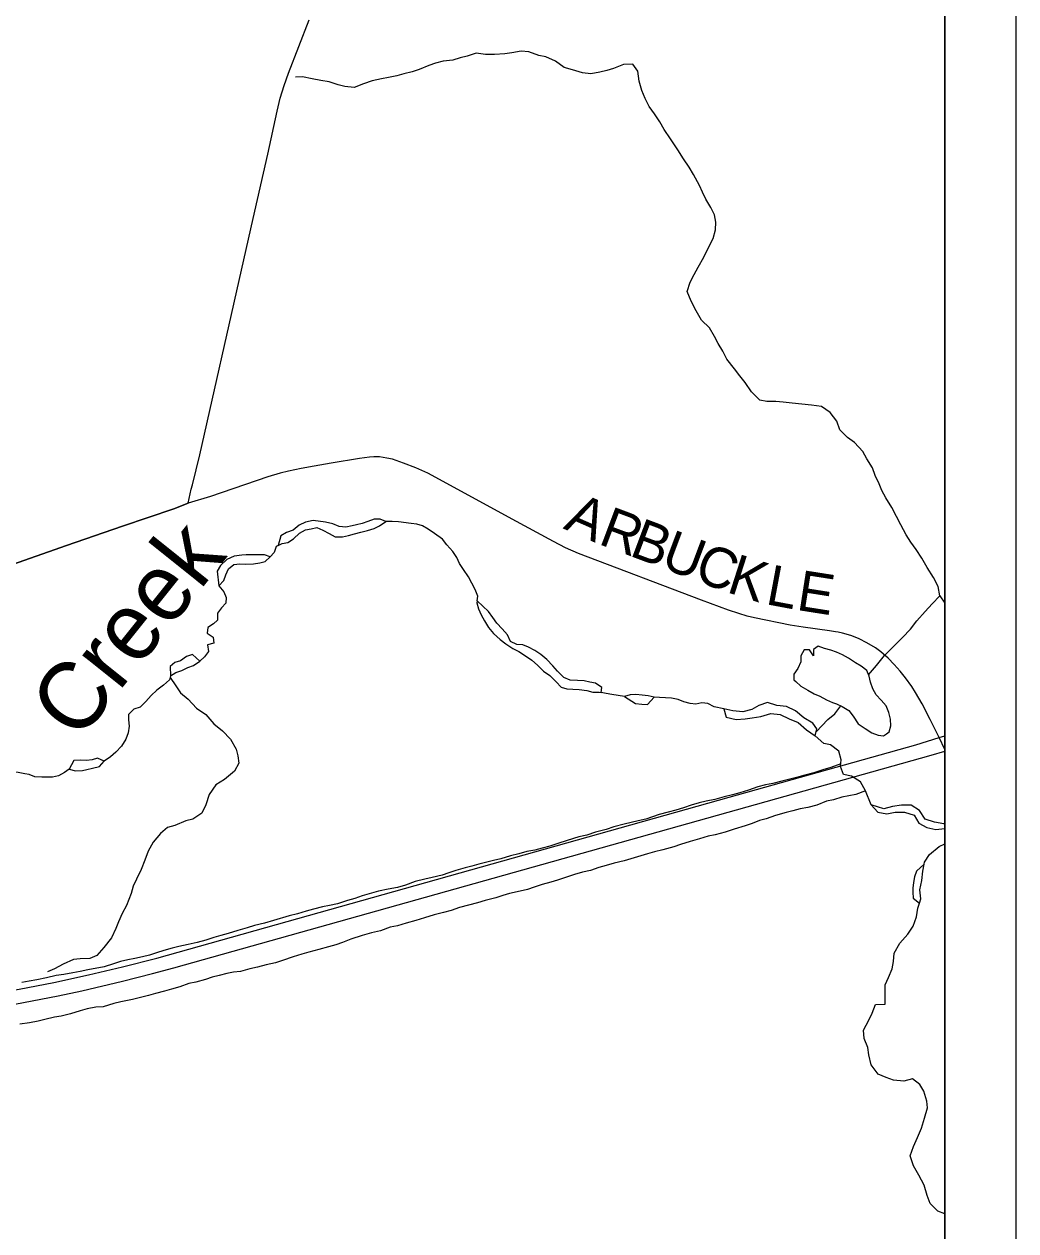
# Model space of a CAD drawing. Extents: x 0 to 36.5, y 0 to 25.3.
# Drawn here: x 7.602 to 9, y 17.597 to 19.299 of the extents above; entities that cross this region are included whole.
import ezdxf

# ---------------------------------------------------------------- set-up
doc = ezdxf.new("R2010")
doc.units = 0
for name, color, linetype in [('DV_X_Township_Line', 7, 'Continuous'), ('GM_X_County_Road', 7, 'Continuous'), ('GM_X_County_Road_Text', 7, 'Continuous'), ('GM_X_Interstate_Route', 7, 'Continuous'), ('GM_X_Major_River', 7, 'Continuous'), ('GM_X_Major_River_Text', 7, 'Continuous'), ('GM_X_Minor_Lake', 7, 'Continuous'), ('GM_X_Minor_River', 7, 'Continuous'), ('GM_X_State_Route', 7, 'Continuous'), ('SH_Cut_Line', 7, 'Continuous'), ('SH_Data', 7, 'Continuous')]:
    doc.layers.add(name, color=color, linetype=linetype)

msp = doc.modelspace()

# ---------------------------------------------------------------- linework, layer by layer
at = {"layer": 'DV_X_Township_Line'}
msp.add_lwpolyline([(8.9, 14.8674), (8.9, 20.9), (6.9868, 20.9), (6.9145, 19.9406), (6.7968, 18.6079), (6.7478, 17.9113), (6.7464, 17.8914), (6.7165, 17.4645), (6.7158, 17.4536), (6.6079, 15.9978), (6.8419, 15.8878), (7.703, 15.458), (7.7552, 15.432), (7.7814, 15.4189), (7.8139, 15.4027), (8.0723, 15.2737), (8.5228, 15.0526)], close=True, dxfattribs=at)
at = {"layer": 'GM_X_County_Road'}
for points in [[(8.7456, 18.4416), (8.7371, 18.4431), (8.7003, 18.448), (8.6819, 18.451), (8.6313, 18.4615), (8.6212, 18.4639), (8.6093, 18.4673), (8.5947, 18.4723), (8.5568, 18.4864), (8.3835, 18.5523), (8.3649, 18.5603), (8.348, 18.5689), (8.2899, 18.6003), (8.1927, 18.6538), (8.1709, 18.6653), (8.154, 18.6729), (8.1368, 18.6796), (8.1209, 18.6849), (8.1132, 18.6867), (8.1026, 18.6882), (8.0947, 18.6883), (8.0886, 18.6879), (8.0747, 18.6862), (8.0344, 18.6797), (8.0104, 18.6754), (7.9925, 18.672), (7.9746, 18.6682), (7.9628, 18.6653), (7.9453, 18.6601), (7.8645, 18.6327), (7.8329, 18.6231)], [(7.8329, 18.6231), (7.8129, 18.6149), (7.7406, 18.5907), (7.6614, 18.5636), (7.55, 18.5246), (7.4901, 18.5041)], [(8.9, 18.2759), (8.8917, 18.2927), (8.8791, 18.318), (8.8677, 18.34), (8.8584, 18.3561), (8.8531, 18.3644), (8.8444, 18.3766), (8.8368, 18.3863), (8.8286, 18.3956), (8.8199, 18.4044), (8.8095, 18.4134), (8.802, 18.419), (8.7901, 18.4263), (8.7789, 18.4319), (8.7732, 18.4342), (8.7674, 18.4363), (8.7554, 18.4396), (8.7494, 18.441), (8.7456, 18.4416)]]:
    msp.add_lwpolyline(points, dxfattribs=at)
at = {"layer": 'GM_X_Interstate_Route'}
for points in [[(6.2743, 17.9219), (6.7481, 17.9108), (7.1122, 17.9021), (7.1623, 17.9009), (7.1809, 17.9008), (7.2306, 17.9013), (7.2616, 17.9022), (7.2989, 17.9039), (7.3609, 17.9079), (7.398, 17.9109), (7.4475, 17.9161), (7.5029, 17.923), (7.5582, 17.9316), (7.5949, 17.938), (7.6437, 17.9474), (7.6923, 17.9578), (7.7406, 17.9692), (7.7887, 17.9816), (8.5958, 18.2085), (8.859, 18.2822), (8.8917, 18.2927), (8.9, 18.2951)], [(7.1025, 17.8824), (7.1065, 17.8823), (7.162, 17.881), (7.1931, 17.881), (7.2179, 17.8813), (7.2552, 17.8823), (7.2924, 17.8836), (7.3479, 17.887), (7.3916, 17.8905), (7.4533, 17.8971), (7.5027, 17.9033), (7.5457, 17.9096), (7.5886, 17.9168), (7.6497, 17.9284), (7.6832, 17.9355), (7.7405, 17.9489), (7.7826, 17.9598), (7.8126, 17.968), (8.8804, 18.2679), (8.9, 18.2733)]]:
    msp.add_lwpolyline(points, dxfattribs=at)
at = {"layer": 'GM_X_Major_River'}
for points in [[(8.1115, 18.597), (8.1039, 18.6004), (8.0951, 18.6005), (8.0864, 18.5974), (8.0784, 18.5944), (8.0704, 18.5926), (8.064, 18.591), (8.0552, 18.5892), (8.0461, 18.5903), (8.037, 18.5938), (8.0268, 18.5961), (8.0093, 18.5984), (7.9986, 18.5962), (7.9895, 18.592), (7.9811, 18.5852), (7.9716, 18.5818), (7.9636, 18.5769), (7.96, 18.5635)], [(8.2403, 18.4854), (8.2414, 18.4921), (8.2377, 18.5013), (8.2327, 18.5104), (8.2282, 18.5191), (8.221, 18.5294), (8.2157, 18.5378), (8.2116, 18.5466), (8.2063, 18.5549), (8.1976, 18.5641), (8.1915, 18.5721), (8.1805, 18.5801), (8.1714, 18.5866), (8.1635, 18.5911), (8.1555, 18.5934), (8.1472, 18.5942), (8.1297, 18.5966), (8.1206, 18.5973), (8.1115, 18.597)], [(7.96, 18.5635), (7.9655, 18.5662), (7.9735, 18.5674), (7.9815, 18.573), (7.9899, 18.5806), (7.9982, 18.5855), (8.0062, 18.587), (8.0146, 18.5889), (8.0229, 18.5851), (8.032, 18.5801), (8.0404, 18.5755), (8.0506, 18.5755), (8.059, 18.5774), (8.0677, 18.58), (8.0765, 18.5823), (8.086, 18.5845), (8.0951, 18.5872), (8.1027, 18.5913), (8.1115, 18.597)], [(7.96, 18.5635), (7.9571, 18.5621), (7.9541, 18.5537), (7.9487, 18.5473)], [(7.9487, 18.5473), (7.9408, 18.55), (7.9309, 18.5504), (7.9233, 18.55), (7.9146, 18.5501), (7.9085, 18.5497), (7.8978, 18.5482), (7.8876, 18.5437), (7.8784, 18.535), (7.8739, 18.527), (7.8761, 18.5065)], [(7.8761, 18.5065), (7.8833, 18.514), (7.886, 18.522), (7.8898, 18.5304), (7.8974, 18.5364), (7.9058, 18.5375), (7.9141, 18.5371), (7.9252, 18.5375), (7.9339, 18.539), (7.9415, 18.5409), (7.9487, 18.5473)], [(7.8761, 18.5065), (7.8833, 18.4981), (7.8867, 18.4901), (7.8859, 18.4821), (7.8798, 18.4753), (7.8741, 18.4681), (7.8744, 18.4582), (7.8687, 18.4529), (7.8607, 18.4476), (7.8599, 18.44), (7.8683, 18.4343)], [(8.2403, 18.4854), (8.2399, 18.4826), (8.2421, 18.4743), (8.2463, 18.4655), (8.2508, 18.4571), (8.2565, 18.4476), (8.2637, 18.4392), (8.2728, 18.4309), (8.2811, 18.4247), (8.2906, 18.4183), (8.2993, 18.4137), (8.3084, 18.408), (8.3175, 18.4015), (8.3255, 18.3946), (8.3342, 18.3862), (8.3429, 18.3801), (8.352, 18.3713), (8.3588, 18.3637), (8.3671, 18.3614), (8.3755, 18.361), (8.3842, 18.3602), (8.3952, 18.3587), (8.4036, 18.3568), (8.4127, 18.3564), (8.4153, 18.3559)], [(8.4153, 18.3559), (8.4161, 18.3632), (8.4074, 18.3693), (8.3995, 18.3708), (8.3911, 18.3724), (8.382, 18.3732), (8.3717, 18.3736), (8.3626, 18.3774), (8.3535, 18.3862), (8.3471, 18.3938), (8.3388, 18.4025), (8.3301, 18.4098), (8.3217, 18.4151), (8.313, 18.4201), (8.3047, 18.4232), (8.2963, 18.4236), (8.2876, 18.4282), (8.283, 18.4373), (8.2755, 18.446), (8.2683, 18.454), (8.2626, 18.462), (8.2562, 18.4704), (8.2403, 18.4854)], [(7.8683, 18.4343), (7.869, 18.4255), (7.8602, 18.4233), (7.8617, 18.4138), (7.856, 18.4062), (7.8495, 18.4005)], [(7.8495, 18.4005), (7.8389, 18.4097), (7.8306, 18.407), (7.8222, 18.4006), (7.8142, 18.3983), (7.8077, 18.393), (7.8081, 18.3797)], [(7.8081, 18.3797), (7.8157, 18.3843), (7.8241, 18.3873), (7.8324, 18.3914), (7.8404, 18.3941), (7.8495, 18.4005)], [(7.8081, 18.3797), (7.8065, 18.374), (7.7982, 18.3664), (7.789, 18.3596), (7.781, 18.3517), (7.7734, 18.3433), (7.7654, 18.3354), (7.7563, 18.3327), (7.749, 18.3252), (7.749, 18.3176), (7.7498, 18.3088), (7.7486, 18.2993), (7.7451, 18.2902), (7.739, 18.2803), (7.731, 18.272), (7.7234, 18.2656), (7.7147, 18.2591)], [(8.4484, 18.3506), (8.4393, 18.3517), (8.4305, 18.3533), (8.4222, 18.3548), (8.4153, 18.3559)], [(8.4898, 18.3497), (8.4814, 18.3516), (8.4731, 18.3524), (8.4644, 18.3532), (8.4564, 18.3528), (8.4484, 18.3506)], [(8.4484, 18.3506), (8.4639, 18.3406), (8.4727, 18.3398), (8.4806, 18.3394), (8.4898, 18.3497)], [(8.5883, 18.3332), (8.5748, 18.3361), (8.5657, 18.3407), (8.5574, 18.3415), (8.549, 18.3396), (8.541, 18.3404), (8.5319, 18.3431), (8.524, 18.3462), (8.5145, 18.3481), (8.5061, 18.3485), (8.4974, 18.3489), (8.4898, 18.3497)], [(8.7171, 18.2948), (8.7193, 18.3047), (8.7135, 18.3131), (8.701, 18.3204), (8.6893, 18.3304), (8.6764, 18.3366), (8.6631, 18.3378), (8.6499, 18.3418), (8.6377, 18.3377), (8.6278, 18.3321), (8.6148, 18.3288), (8.6011, 18.3304), (8.5883, 18.3332)], [(8.5883, 18.3332), (8.5916, 18.3214), (8.6056, 18.3182), (8.6185, 18.3188), (8.628, 18.3203), (8.6406, 18.3221), (8.6543, 18.3265), (8.6676, 18.3249), (8.6805, 18.3191), (8.6929, 18.3136), (8.705, 18.3036), (8.7171, 18.2948)], [(8.7961, 18.1979), (8.7878, 18.2174), (8.7811, 18.23), (8.7683, 18.2381), (8.7569, 18.2405), (8.7528, 18.2519), (8.7536, 18.2614), (8.7503, 18.2736), (8.7386, 18.2821), (8.7292, 18.2841), (8.7171, 18.2948)], [(7.7147, 18.2591), (7.7052, 18.2633), (7.6976, 18.2611), (7.6896, 18.26), (7.6809, 18.2607), (7.6717, 18.26), (7.6653, 18.2479)], [(7.6653, 18.2479), (7.674, 18.2456), (7.6839, 18.2459), (7.6899, 18.2474), (7.6983, 18.2493), (7.7078, 18.2516), (7.7147, 18.2591)], [(7.6653, 18.2479), (7.6584, 18.2433), (7.65, 18.2384), (7.6417, 18.2365), (7.6265, 18.2366), (7.617, 18.2374), (7.6086, 18.2404), (7.6026, 18.2416), (7.5931, 18.2435), (7.5847, 18.2439), (7.5764, 18.2432), (7.5676, 18.2451), (7.5593, 18.2467), (7.5467, 18.244)], [(8.7961, 18.1979), (8.8054, 18.1872), (8.8179, 18.1852), (8.8297, 18.1874), (8.843, 18.1873), (8.8567, 18.1833), (8.863, 18.1719), (8.8744, 18.1657), (8.8873, 18.1629), (8.8998, 18.1643), (8.9, 18.1638)], [(8.9, 18.1701), (8.8983, 18.1708), (8.8855, 18.1732), (8.8722, 18.1775), (8.8639, 18.1897), (8.8522, 18.1971), (8.8389, 18.1972), (8.826, 18.1954), (8.8138, 18.1921), (8.7961, 18.1979)], [(8.8707, 18.114), (8.8713, 18.1171), (8.8782, 18.1277), (8.8919, 18.1392), (8.9, 18.1427)], [(8.8707, 18.114), (8.8601, 18.1043), (8.8571, 18.0963), (8.8555, 18.0883), (8.8548, 18.0804), (8.8547, 18.0747), (8.8551, 18.0659), (8.8642, 18.0592)], [(8.8642, 18.0592), (8.8662, 18.0651), (8.8648, 18.078), (8.8676, 18.0909), (8.8689, 18.1042), (8.8707, 18.114)], [(8.9, 17.6209), (8.89, 17.6246), (8.8794, 17.6354), (8.875, 17.6468), (8.8706, 17.6613), (8.8631, 17.6754), (8.8556, 17.6888), (8.8508, 17.7029), (8.8555, 17.7158), (8.8613, 17.7287), (8.8671, 17.7419), (8.8714, 17.7559), (8.8753, 17.7704), (8.8747, 17.7799), (8.8702, 17.794), (8.8646, 17.8035), (8.8541, 17.8112), (8.8419, 17.8079), (8.8274, 17.8096), (8.8172, 17.8131), (8.8059, 17.8181), (8.7961, 17.8311), (8.7928, 17.8452), (8.7914, 17.8555), (8.7862, 17.8681), (8.7852, 17.8799), (8.7925, 17.8939), (8.7972, 17.9041), (8.8022, 17.9162), (8.8155, 17.9165), (8.8157, 17.9438), (8.8204, 17.9541), (8.8255, 17.9666), (8.8274, 17.9768), (8.8283, 17.9886), (8.8364, 18.0026), (8.8479, 18.0154), (8.8553, 18.0268), (8.8599, 18.0396), (8.8616, 18.0518), (8.8642, 18.0592)]]:
    msp.add_lwpolyline(points, dxfattribs=at)
at = {"layer": 'GM_X_Minor_Lake'}
for points in [[(8.8174, 18.2979), (8.8212, 18.3005), (8.8235, 18.3092), (8.8232, 18.3187), (8.8209, 18.3279), (8.8172, 18.3374), (8.81, 18.3454), (8.8028, 18.353), (8.7983, 18.3614), (8.7949, 18.3709), (8.793, 18.3793), (8.79, 18.3872), (8.782, 18.3933), (8.7737, 18.3979), (8.7642, 18.4044), (8.7555, 18.4094), (8.7471, 18.4128), (8.7392, 18.4159), (8.7301, 18.4182), (8.7213, 18.4216), (8.7149, 18.4167), (8.7148, 18.4076), (8.7092, 18.4163), (8.7016, 18.4164), (8.6966, 18.408), (8.6966, 18.3993), (8.6927, 18.3898), (8.687, 18.3818), (8.687, 18.3742)], [(8.687, 18.3742), (8.6897, 18.3716), (8.6968, 18.3651), (8.7067, 18.3594), (8.7154, 18.3544), (8.7238, 18.3509), (8.7329, 18.346), (8.7416, 18.3422), (8.7473, 18.3399), (8.7549, 18.3364), (8.7647, 18.3307), (8.7708, 18.3227), (8.7776, 18.312), (8.7874, 18.3052), (8.7969, 18.2991), (8.8057, 18.296), (8.8136, 18.2952), (8.8174, 18.2979)]]:
    msp.add_lwpolyline(points, dxfattribs=at)
at = {"layer": 'GM_X_Minor_River'}
msp.add_line((8.8928, 18.4922), (8.9, 18.4823), dxfattribs=at)
for points in [[(8.206, 19.2476), (8.1924, 19.2461), (8.1817, 19.2435), (8.1722, 19.2401), (8.1585, 19.2345), (8.1486, 19.2314), (8.1372, 19.2284), (8.127, 19.2258), (8.1156, 19.2232), (8.1057, 19.2213), (8.0924, 19.2187), (8.0802, 19.2145), (8.0669, 19.2093), (8.054, 19.2104), (8.0445, 19.2131), (8.032, 19.217), (8.0202, 19.2189), (8.0077, 19.2212), (7.994, 19.2243), (7.9842, 19.2239)], [(8.7923, 18.3812), (8.8037, 18.394), (8.8147, 18.4085), (8.8265, 18.4202), (8.8403, 18.4335), (8.8513, 18.4452), (8.8605, 18.457), (8.8723, 18.4702), (8.8822, 18.4812), (8.8928, 18.4922), (8.8906, 18.5055), (8.8838, 18.5181), (8.8751, 18.5322), (8.8672, 18.5455), (8.8592, 18.5577), (8.8517, 18.5683), (8.8452, 18.5782), (8.8377, 18.5923), (8.8316, 18.6041), (8.8252, 18.6171), (8.8165, 18.6308), (8.8112, 18.6407), (8.8071, 18.6502), (8.8014, 18.6623), (8.7977, 18.673), (8.7897, 18.6856), (8.7841, 18.6958), (8.7723, 18.7084), (8.7625, 18.7156), (8.7519, 18.7267), (8.7477, 18.7385), (8.7383, 18.7511), (8.7261, 18.7594), (8.7117, 18.7614), (8.698, 18.7626), (8.6844, 18.7641), (8.6718, 18.7657), (8.6616, 18.7665), (8.649, 18.7665), (8.6388, 18.7684), (8.6274, 18.7799), (8.6184, 18.7932), (8.6108, 18.8027), (8.6032, 18.8126), (8.5926, 18.8259), (8.587, 18.8373), (8.5802, 18.8484), (8.5749, 18.8579), (8.5681, 18.8701), (8.5567, 18.8811), (8.5491, 18.8944), (8.542, 18.9081), (8.5367, 18.9215), (8.5409, 18.9347), (8.5463, 18.9454), (8.552, 18.956), (8.56, 18.97), (8.5657, 18.9818), (8.5734, 18.9962), (8.5764, 19.0084), (8.5772, 19.0194), (8.575, 19.0296), (8.5701, 19.0399), (8.5629, 19.0517), (8.5584, 19.0616), (8.5538, 19.0711), (8.5455, 19.0867), (8.5395, 19.097), (8.5312, 19.1088), (8.5232, 19.1213), (8.513, 19.137), (8.5043, 19.1499), (8.4979, 19.1609), (8.4907, 19.172), (8.4831, 19.1822), (8.4771, 19.1937), (8.4726, 19.2051), (8.4688, 19.218), (8.4669, 19.2321), (8.4598, 19.242), (8.4468, 19.2416), (8.4328, 19.236), (8.4233, 19.2333), (8.4134, 19.2307), (8.4005, 19.2285), (8.3891, 19.23), (8.375, 19.2342), (8.3633, 19.2373), (8.3508, 19.2464), (8.3375, 19.2522), (8.3272, 19.2545), (8.3132, 19.2595), (8.3026, 19.2606), (8.2893, 19.258), (8.2794, 19.2565), (8.2649, 19.2558), (8.2524, 19.2558), (8.2391, 19.2578), (8.2262, 19.2533), (8.2167, 19.251), (8.206, 19.2476)], [(7.8077, 18.3774), (7.8156, 18.3653), (7.8221, 18.3557), (7.8331, 18.3466), (7.8448, 18.334), (7.8577, 18.3252), (7.869, 18.3119), (7.8812, 18.302), (7.8925, 18.2902), (7.9008, 18.2761), (7.9031, 18.2666), (7.9046, 18.2563), (7.8985, 18.2453), (7.8844, 18.2336), (7.8718, 18.226), (7.8627, 18.2123), (7.8581, 18.1979), (7.8523, 18.1861), (7.8394, 18.1774), (7.8295, 18.1752), (7.8143, 18.1688), (7.804, 18.1658), (7.7941, 18.1574), (7.7834, 18.1449), (7.7766, 18.1324), (7.772, 18.1199), (7.7666, 18.1066), (7.7601, 18.0929), (7.7555, 18.083), (7.7528, 18.0728), (7.746, 18.0557), (7.7398, 18.0443), (7.7349, 18.0329), (7.731, 18.0234), (7.7249, 18.0102), (7.7139, 17.9965), (7.7043, 17.9851), (7.6944, 17.981), (7.6808, 17.9806), (7.6713, 17.9795), (7.6568, 17.9731), (7.6443, 17.9663), (7.6348, 17.9621)], [(8.7184, 18.3005), (8.7347, 18.3182), (8.7446, 18.3262), (8.7532, 18.3372)], [(8.7531, 18.2553), (8.739, 18.2502), (8.728, 18.2472), (8.7151, 18.243), (8.7006, 18.2393), (8.6908, 18.2363), (8.6813, 18.234), (8.6702, 18.231), (8.6573, 18.2276), (8.6471, 18.2257), (8.6364, 18.2231), (8.6231, 18.2186), (8.6109, 18.2148), (8.6003, 18.2118), (8.5889, 18.2088), (8.5756, 18.2054), (8.5634, 18.2028), (8.5535, 18.2005), (8.5421, 18.1971), (8.5315, 18.1934), (8.5205, 18.19), (8.5098, 18.1873), (8.4973, 18.184), (8.4878, 18.1806), (8.4783, 18.1776), (8.4676, 18.1753), (8.4574, 18.1727), (8.4475, 18.1704), (8.433, 18.1667), (8.4224, 18.1629), (8.4072, 18.1591), (8.395, 18.155), (8.384, 18.1527), (8.3673, 18.1475), (8.3543, 18.1433), (8.3429, 18.1395), (8.3323, 18.1365), (8.3216, 18.1339), (8.3106, 18.132), (8.2992, 18.1286), (8.2874, 18.126), (8.2737, 18.1215), (8.2635, 18.1192), (8.2521, 18.1162), (8.2426, 18.114), (8.2331, 18.1113), (8.2236, 18.1091), (8.2103, 18.1053), (8.2004, 18.1019), (8.1909, 18.0985), (8.1772, 18.0952), (8.1669, 18.0929), (8.1532, 18.0895), (8.1392, 18.0846), (8.1281, 18.0812), (8.1152, 18.0786), (8.1015, 18.076), (8.0917, 18.073), (8.0783, 18.0696), (8.0681, 18.0658), (8.0578, 18.0628), (8.0437, 18.0583), (8.0323, 18.0557), (8.0225, 18.0538), (8.0095, 18.0508), (7.9993, 18.0478), (7.9871, 18.044), (7.9753, 18.0414), (7.9533, 18.0346), (7.9407, 18.0308), (7.9263, 18.0274), (7.916, 18.0244), (7.9031, 18.0207), (7.8894, 18.0165), (7.8788, 18.0135), (7.8693, 18.0105), (7.8579, 18.0071), (7.8457, 18.0037), (7.8328, 18.0007), (7.8198, 17.9981), (7.8103, 17.9958), (7.7986, 17.9925), (7.7883, 17.9891), (7.7784, 17.9857), (7.7685, 17.9834), (7.7579, 17.9812), (7.748, 17.9793), (7.7374, 17.9767), (7.7275, 17.9737), (7.7145, 17.9695), (7.6917, 17.965), (7.6807, 17.9628), (7.6705, 17.9609), (7.6575, 17.9583), (7.6469, 17.9572), (7.6332, 17.9538), (7.6195, 17.9508), (7.6089, 17.9489), (7.5986, 17.947)], [(8.7878, 18.2174), (8.7743, 18.2125), (8.7644, 18.2102), (8.7545, 18.2083), (8.7427, 18.2046), (8.7332, 18.2027), (8.7195, 18.1974), (8.7066, 18.194), (8.6959, 18.1922), (8.6857, 18.1891), (8.6762, 18.1869), (8.661, 18.1828), (8.648, 18.1782), (8.6385, 18.1756), (8.6283, 18.1714), (8.6184, 18.168), (8.6028, 18.1635), (8.5899, 18.1594), (8.5758, 18.1556), (8.5663, 18.1534), (8.5541, 18.15), (8.5408, 18.1458), (8.5271, 18.1417), (8.5176, 18.1387), (8.5024, 18.1345), (8.4903, 18.1315), (8.4808, 18.1285), (8.4713, 18.1259), (8.4572, 18.1217), (8.4477, 18.1187), (8.4336, 18.1153), (8.4222, 18.112), (8.412, 18.1093), (8.4002, 18.1052), (8.3891, 18.1029), (8.3777, 18.0995), (8.3538, 18.0916), (8.3443, 18.0886), (8.3321, 18.0856), (8.3207, 18.0818), (8.3112, 18.0784), (8.3009, 18.0762), (8.2861, 18.0728), (8.2766, 18.0698), (8.2667, 18.0664), (8.2515, 18.063), (8.2409, 18.0596), (8.228, 18.0562), (8.2154, 18.0529), (8.204, 18.0487), (8.193, 18.0457), (8.1797, 18.0427), (8.1664, 18.0386), (8.1542, 18.0348), (8.1405, 18.031), (8.128, 18.0273), (8.1177, 18.025), (8.104, 18.0201), (8.0915, 18.0171), (8.0782, 18.0133), (8.0622, 18.0081), (8.0508, 18.0035), (8.0413, 18.0005), (8.031, 17.9975), (8.017, 17.9937), (8.0033, 17.99), (7.9934, 17.987), (7.9808, 17.9832), (7.966, 17.9783), (7.9561, 17.9749), (7.9428, 17.9723), (7.9307, 17.9689), (7.92, 17.9663), (7.9067, 17.9629), (7.8968, 17.9618), (7.8873, 17.9599), (7.8767, 17.9573), (7.8668, 17.9546), (7.8573, 17.9516), (7.844, 17.9479), (7.8341, 17.9456), (7.8212, 17.9411), (7.8094, 17.9377), (7.7995, 17.9351), (7.787, 17.9317), (7.7771, 17.929), (7.7543, 17.9234), (7.7379, 17.92), (7.7281, 17.9178), (7.7129, 17.9129), (7.703, 17.9122), (7.6904, 17.9099), (7.6806, 17.9073), (7.6672, 17.9031), (7.6539, 17.8997), (7.6444, 17.8983), (7.6311, 17.8949), (7.6213, 17.8926), (7.6091, 17.8904), (7.5958, 17.8885)]]:
    msp.add_lwpolyline(points, dxfattribs=at)
at = {"layer": 'GM_X_State_Route'}
for points in [[(7.8329, 18.6231), (7.8373, 18.6429), (7.839, 18.6488), (7.8494, 18.691), (7.9081, 18.9516), (7.9247, 19.0243), (7.9451, 19.1152), (7.9584, 19.1759), (7.9629, 19.1939), (7.9683, 19.2118), (7.9746, 19.2293), (8.0036, 19.3047)], [(7.4901, 18.5041), (7.55, 18.5246), (7.6614, 18.5636), (7.7406, 18.5907), (7.8129, 18.6149), (7.8329, 18.6231)]]:
    msp.add_lwpolyline(points, dxfattribs=at)
at = {"layer": 'SH_Cut_Line'}
msp.add_lwpolyline([(4.4591, 20.9), (3.3366, 20.9), (3.2612, 20.6041), (2.8463, 19.037), (2.6265, 18.2595), (2.5271, 17.8912), (2.5226, 17.8751), (2.5165, 17.8524), (2.5144, 17.8445), (2.4192, 17.4891), (2.3437, 17.2326), (2.3403, 17.2198), (2.1039, 16.2931), (2.1, 16.2788), (2.1, 14.1), (8.9, 14.1), (8.9, 20.9), (6.1845, 20.9)], dxfattribs=at)
at = {"layer": 'SH_Data'}
for p, q in [((9, 21), (9, 14)), ((8.9, 20.9), (8.9, 14.1))]:
    msp.add_line(p, q, dxfattribs=at)

# ---------------------------------------------------------------- texts
at = {"layer": 'GM_X_County_Road_Text'}
for s, rotation, p in [('A', 336.1533, (8.3608, 18.5876)), ('R', 339.3761, (8.4097, 18.5661)), ('B', 339.3663, (8.4534, 18.5496)), ('U', 339.3655, (8.4971, 18.5332)), ('C', 339.4057, (8.5439, 18.5155)), ('K', 342.2279, (8.5905, 18.4981)), ('L', 349.3871, (8.6456, 18.481)), ('E', 351.0882, (8.6892, 18.4728))]:
    msp.add_text(s, height=0.0568, rotation=rotation, dxfattribs=at).set_placement(p)
at = {"layer": 'GM_X_Major_River_Text'}
msp.add_text('Creek', height=0.09471, rotation=51.3036, dxfattribs=at).set_placement((7.6778, 18.2849))

doc.saveas('drawing.dxf')
